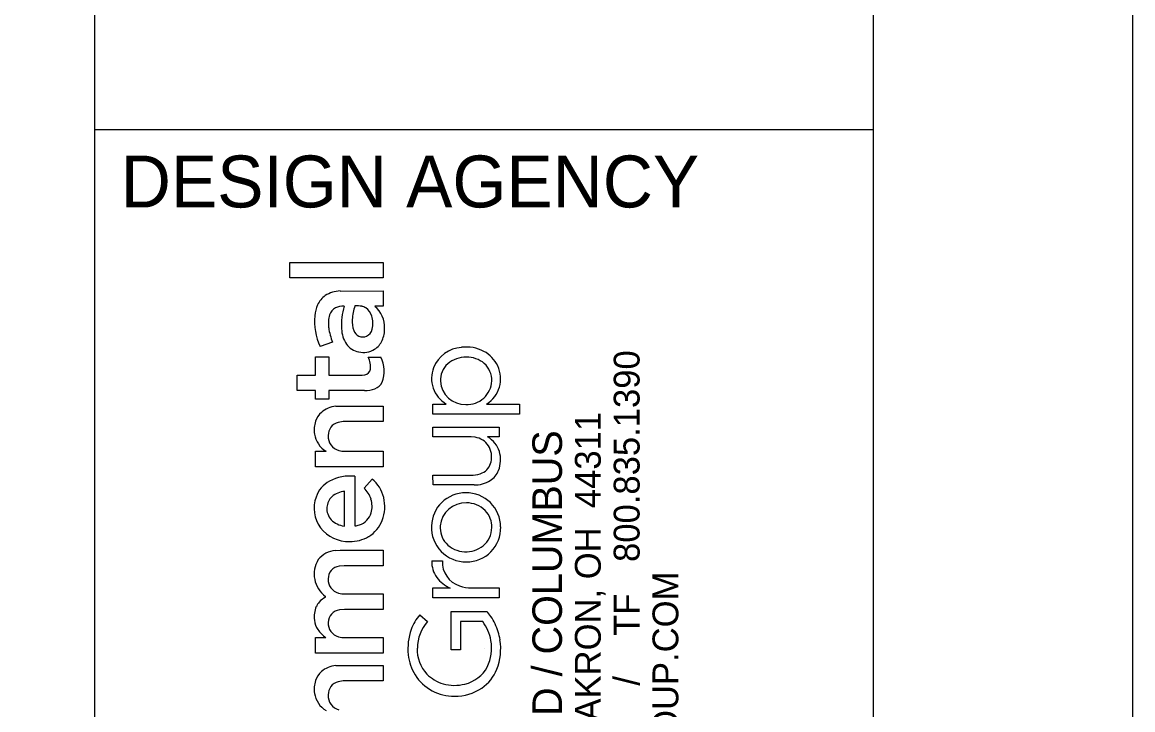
# Model space of a CAD drawing. Extents: x -0.2 to 34, y 0 to 22.
# Drawn here: x 31.86 to 34, y 3.382 to 4.707 of the extents above; entities that cross this region are included whole.
import ezdxf

# ---------------------------------------------------------------- set-up
doc = ezdxf.new("R2010")
doc.units = 0
for name, color, linetype in [('SH_Border', 7, 'Continuous'), ('SH_Cut_Line', 7, 'Continuous'), ('SH_Data', 7, 'Continuous')]:
    doc.layers.add(name, color=color, linetype=linetype)

msp = doc.modelspace()

# ---------------------------------------------------------------- linework, layer by layer
at = {"layer": 'SH_Border'}
for p, q in [((32, 0.5), (32, 21.5)), ((32, 4.5), (33.5, 4.5))]:
    msp.add_line(p, q, dxfattribs=at)
msp.add_lwpolyline([(1.5, 21.5), (33.5, 21.5), (33.5, 0.5), (1.5, 0.5)], close=True, dxfattribs=at)
at = {"layer": 'SH_Cut_Line'}
msp.add_lwpolyline([(0, 0), (34, 0), (34, 22), (0, 22)], close=True, dxfattribs=at)
at = {"layer": 'SH_Data'}
for p, q in [((32.3756, 4.2141), (32.3756, 4.244)), ((32.3756, 4.244), (32.5557, 4.244)), ((32.5557, 4.244), (32.5557, 4.2141)), ((32.5557, 4.2141), (32.3756, 4.2141)), ((32.4727, 4.189), (32.5555, 4.1892)), ((32.5555, 4.1892), (32.5557, 4.1596)), ((32.5557, 4.1596), (32.5397, 4.1596)), ((32.4582, 4.0904), (32.4343, 4.0823)), ((32.4254, 4.027), (32.4255, 4.0621)), ((32.4255, 4.0621), (32.4511, 4.0621)), ((32.4511, 4.0621), (32.4512, 4.027)), ((32.527, 4.0616), (32.5511, 4.0616)), ((32.3896, 3.9972), (32.3896, 4.027)), ((32.3896, 4.027), (32.4254, 4.027)), ((32.4512, 4.027), (32.515, 4.027)), ((32.515, 4.027), (32.52, 4.0275)), ((32.4254, 3.9972), (32.3896, 3.9972)), ((32.4254, 3.9807), (32.4254, 3.9972)), ((32.4511, 3.9807), (32.4254, 3.9807)), ((32.5197, 3.9972), (32.4511, 3.9972)), ((32.4511, 3.9972), (32.4511, 3.9807)), ((32.4644, 3.9669), (32.4729, 3.9673)), ((32.4729, 3.9673), (32.5557, 3.9673)), ((32.5557, 3.9673), (32.5557, 3.9375)), ((32.6515, 3.9521), (32.6515, 3.9711)), ((32.6515, 3.9711), (32.6771, 3.9711)), ((32.7549, 3.9713), (32.8186, 3.9711)), ((32.8186, 3.9711), (32.8184, 3.9521)), ((32.5557, 3.9375), (32.4814, 3.9375)), ((32.8184, 3.9521), (32.6515, 3.9521)), ((32.6515, 3.908), (32.6515, 3.9267)), ((32.6515, 3.9267), (32.7791, 3.9266)), ((32.7791, 3.9266), (32.7791, 3.908)), ((32.7249, 3.908), (32.6515, 3.908)), ((32.7328, 3.9073), (32.7249, 3.908)), ((32.7791, 3.908), (32.7569, 3.908)), ((32.4254, 3.8503), (32.4254, 3.8802)), ((32.4254, 3.8802), (32.4455, 3.8802)), ((32.4822, 3.8802), (32.5557, 3.8802)), ((32.5557, 3.8802), (32.5557, 3.8504)), ((32.5557, 3.8504), (32.4254, 3.8503)), ((32.5011, 3.8321), (32.5012, 3.7366)), ((32.6515, 3.8344), (32.7291, 3.8345)), ((32.6517, 3.8154), (32.6515, 3.8344)), ((32.5188, 3.8093), (32.5342, 3.8266)), ((32.7307, 3.8154), (32.6517, 3.8154)), ((32.4814, 3.7364), (32.4814, 3.803)), ((32.4802, 3.7363), (32.4814, 3.7364)), ((32.4633, 3.6891), (32.4726, 3.6897)), ((32.4726, 3.6897), (32.5556, 3.6897)), ((32.5556, 3.6897), (32.5557, 3.6598)), ((32.4806, 3.6598), (32.471, 3.6588)), ((32.5557, 3.6598), (32.4806, 3.6598)), ((32.6493, 3.6691), (32.6698, 3.6691)), ((32.6515, 3.598), (32.6515, 3.617)), ((32.6515, 3.617), (32.6848, 3.617)), ((32.726, 3.617), (32.7791, 3.617)), ((32.7791, 3.617), (32.779, 3.598)), ((32.4444, 3.5992), (32.4446, 3.6007)), ((32.4822, 3.6055), (32.5557, 3.6055)), ((32.5557, 3.6055), (32.5557, 3.5757)), ((32.779, 3.598), (32.6515, 3.598)), ((32.4809, 3.5757), (32.4714, 3.5747)), ((32.5557, 3.5757), (32.4809, 3.5757)), ((32.6264, 3.5655), (32.6411, 3.5524)), ((32.6868, 3.5718), (32.7552, 3.5719)), ((32.6868, 3.4978), (32.6868, 3.5718)), ((32.7045, 3.5524), (32.7043, 3.4978)), ((32.7474, 3.5523), (32.7045, 3.5524)), ((32.4254, 3.4915), (32.4254, 3.5214)), ((32.4254, 3.5214), (32.4451, 3.5214)), ((32.4821, 3.5214), (32.5557, 3.5214)), ((32.5557, 3.5214), (32.5557, 3.4916)), ((32.5557, 3.4916), (32.4254, 3.4915)), ((32.7043, 3.4978), (32.6868, 3.4978)), ((32.75, 3.5), (32.75, 3.5)), ((32.4644, 3.4674), (32.4729, 3.4678)), ((32.4729, 3.4678), (32.5557, 3.4678)), ((32.5557, 3.4678), (32.5557, 3.438)), ((32.5557, 3.438), (32.4814, 3.438))]:
    msp.add_line(p, q, dxfattribs=at)
msp.add_lwpolyline([(32.3756, 4.2141), (32.3756, 4.244), (32.5557, 4.244), (32.5557, 4.2141)], close=True, dxfattribs=at)
for points in [[(32.4727, 4.189), (32.5555, 4.1892), (32.5557, 4.1596)], [(32.5557, 4.1596), (32.5397, 4.1596)], [(32.4582, 4.0904), (32.4343, 4.0823)], [(32.5197, 3.9972), (32.4511, 3.9972), (32.4511, 3.9807), (32.4254, 3.9807), (32.4254, 3.9972), (32.3896, 3.9972), (32.3896, 4.027), (32.4254, 4.027), (32.4255, 4.0621), (32.4511, 4.0621), (32.4512, 4.027), (32.515, 4.027), (32.52, 4.0275)], [(32.527, 4.0616), (32.5511, 4.0616)], [(32.4644, 3.9669), (32.4729, 3.9673), (32.5557, 3.9673), (32.5557, 3.9375), (32.4814, 3.9375)], [(32.7549, 3.9713), (32.8186, 3.9711), (32.8184, 3.9521), (32.6515, 3.9521)], [(32.6515, 3.9521), (32.6515, 3.9711), (32.6771, 3.9711)], [(32.7328, 3.9073), (32.7249, 3.908), (32.6515, 3.908), (32.6515, 3.9267), (32.7791, 3.9266), (32.7791, 3.908), (32.7569, 3.908)], [(32.4254, 3.8503), (32.4254, 3.8802), (32.4455, 3.8802)], [(32.4822, 3.8802), (32.5557, 3.8802), (32.5557, 3.8504), (32.4254, 3.8503)], [(32.5011, 3.8321), (32.5012, 3.7366)], [(32.7307, 3.8154), (32.6517, 3.8154), (32.6515, 3.8344), (32.7291, 3.8345)], [(32.5188, 3.8093), (32.5342, 3.8266)], [(32.4802, 3.7363), (32.4814, 3.7364), (32.4814, 3.803)], [(32.4633, 3.6891), (32.4726, 3.6897), (32.5556, 3.6897), (32.5557, 3.6598), (32.4806, 3.6598), (32.471, 3.6588)], [(32.6493, 3.6691), (32.6698, 3.6691)], [(32.6515, 3.598), (32.6515, 3.617), (32.6848, 3.617)], [(32.726, 3.617), (32.7791, 3.617), (32.779, 3.598), (32.6515, 3.598)], [(32.4444, 3.5992), (32.4446, 3.6007)], [(32.4822, 3.6055), (32.5557, 3.6055), (32.5557, 3.5757), (32.4809, 3.5757), (32.4714, 3.5747)], [(32.6264, 3.5655), (32.6411, 3.5524)], [(32.7474, 3.5523), (32.7045, 3.5524), (32.7043, 3.4978), (32.6868, 3.4978), (32.6868, 3.5718), (32.7552, 3.5719)], [(32.4254, 3.4915), (32.4254, 3.5214), (32.4451, 3.5214)], [(32.4821, 3.5214), (32.5557, 3.5214), (32.5557, 3.4916), (32.4254, 3.4915)], [(32.4644, 3.4674), (32.4729, 3.4678), (32.5557, 3.4678), (32.5557, 3.438), (32.4814, 3.438)]]:
    msp.add_lwpolyline(points, dxfattribs=at)
for centre, radius, start, end in [((32.4685, 4.1447), 0.043, 124.537, 155.6594), ((32.4685, 4.1447), 0.043, 124.537, 155.6594), ((32.4745, 4.1326), 0.0565, 91.8942, 122.6317), ((32.4745, 4.1326), 0.0565, 91.8942, 122.6317), ((32.4882, 4.1361), 0.0646, 155.9764, 175.3149), ((32.4882, 4.1361), 0.0646, 155.9764, 175.3149), ((32.4753, 4.1356), 0.024, 119.4252, 161.6629), ((32.4753, 4.1356), 0.024, 119.4252, 161.6629), ((32.4779, 4.1278), 0.0321, 85.3802, 116.6222), ((32.4779, 4.1278), 0.0321, 85.3802, 116.6222), ((32.5879, 4.1251), 0.1129, 162.0821, 184.5285), ((32.5879, 4.1251), 0.1129, 162.0821, 184.5285), ((32.5801, 4.1313), 0.0841, 159.8366, 178.0362), ((32.5801, 4.1313), 0.0841, 159.8366, 178.0362), ((32.5051, 4.1074), 0.053, 79.6696, 94.2322), ((32.5051, 4.1074), 0.053, 79.6696, 94.2322), ((32.5089, 4.1364), 0.0238, 56.8913, 76.2149), ((32.5089, 4.1364), 0.0238, 56.8913, 76.2149), ((32.5052, 4.1318), 0.0297, 17.5984, 55.7282), ((32.5052, 4.1318), 0.0297, 17.5984, 55.7282), ((32.5055, 4.1191), 0.0529, 358.0746, 49.762), ((32.5055, 4.1191), 0.0529, 358.0746, 49.762), ((32.5364, 4.1308), 0.113, 174.6101, 205.3899), ((32.5364, 4.1308), 0.113, 174.6101, 205.3899), ((32.5076, 4.1265), 0.0576, 163.1369, 188.1675), ((32.5076, 4.1265), 0.0576, 163.1369, 188.1675), ((32.5466, 4.1303), 0.0506, 175.5903, 199.8857), ((32.5466, 4.1303), 0.0506, 175.5903, 199.8857), ((32.4916, 4.1264), 0.0443, 345.9408, 18.9919), ((32.4916, 4.1264), 0.0443, 345.9408, 18.9919), ((32.5473, 4.1297), 0.0973, 186.7598, 203.7981), ((32.5473, 4.1297), 0.0973, 186.7598, 203.7981), ((32.5328, 4.1187), 0.0575, 182.5676, 213.7144), ((32.5328, 4.1187), 0.0575, 182.5676, 213.7144), ((32.5164, 4.1189), 0.0184, 198.2844, 293.3081), ((32.5164, 4.1189), 0.0184, 198.2844, 293.3081), ((32.5152, 4.1199), 0.0199, 295.2883, 347.4639), ((32.5152, 4.1199), 0.0199, 295.2883, 347.4639), ((32.5019, 4.1168), 0.0566, 336.016, 0.5951), ((32.5019, 4.1168), 0.0566, 336.016, 0.5951), ((32.5175, 4.1097), 0.0394, 303.4436, 336.18), ((32.5175, 4.1097), 0.0394, 303.4436, 336.18), ((32.5149, 4.1078), 0.0366, 215.0668, 259.8133), ((32.5149, 4.1078), 0.0366, 215.0668, 259.8133), ((32.5175, 4.1131), 0.0423, 257.5256, 300.882), ((32.5175, 4.1131), 0.0423, 257.5256, 300.882), ((32.7108, 4.0182), 0.0624, 93.9866, 158.3119), ((32.7108, 4.0182), 0.0624, 93.9866, 158.3119), ((32.7156, 4.0065), 0.0746, 62.6889, 97.0135), ((32.7156, 4.0065), 0.0746, 62.6889, 97.0135), ((32.7212, 4.0191), 0.0608, 25.0657, 61.9602), ((32.7212, 4.0191), 0.0608, 25.0657, 61.9602), ((32.4863, 4.042), 0.0452, 10.1545, 25.723), ((32.4863, 4.042), 0.0452, 10.1545, 25.723), ((32.4957, 4.0436), 0.0356, 351.914, 10.2059), ((32.4957, 4.0436), 0.0356, 351.914, 10.2059), ((32.503, 4.0351), 0.0549, 336.589, 28.8991), ((32.503, 4.0351), 0.0549, 336.589, 28.8991), ((32.7092, 4.0167), 0.0434, 132.3289, 182.0949), ((32.7092, 4.0167), 0.0434, 132.3289, 182.0949), ((32.7138, 4.0102), 0.0513, 87.8965, 131.1812), ((32.7138, 4.0102), 0.0513, 87.8965, 131.1812), ((32.7175, 4.0102), 0.0513, 49.9089, 92.0363), ((32.7175, 4.0102), 0.0513, 49.9089, 92.0363), ((32.7215, 4.0173), 0.0433, 358.0487, 47.9447), ((32.7215, 4.0173), 0.0433, 358.0487, 47.9447), ((32.7245, 4.02), 0.0574, 301.9776, 25.6418), ((32.7245, 4.02), 0.0574, 301.9776, 25.6418), ((32.5184, 4.04), 0.0126, 277.6142, 353.7918), ((32.5184, 4.04), 0.0126, 277.6142, 353.7918), ((32.707, 4.0202), 0.0581, 158.656, 198.171), ((32.707, 4.0202), 0.0581, 158.656, 198.171), ((32.5291, 4.0261), 0.0275, 292.6889, 332.0598), ((32.5291, 4.0261), 0.0275, 292.6889, 332.0598), ((32.7103, 4.0243), 0.0627, 200.8399, 238.0162), ((32.7103, 4.0243), 0.0627, 200.8399, 238.0162), ((32.7135, 4.0181), 0.0478, 183.5974, 271.7045), ((32.7135, 4.0181), 0.0478, 183.5974, 271.7045), ((32.7172, 4.018), 0.0477, 267.3149, 357.4019), ((32.7172, 4.018), 0.0477, 267.3149, 357.4019), ((32.5209, 4.0486), 0.0514, 268.6727, 291.5235), ((32.5209, 4.0486), 0.0514, 268.6727, 291.5235), ((32.4687, 3.9172), 0.0499, 94.9706, 130.2248), ((32.4687, 3.9172), 0.0499, 94.9706, 130.2248), ((32.4787, 3.9211), 0.056, 162.274, 187.7917), ((32.4787, 3.9211), 0.056, 162.274, 187.7917), ((32.4635, 3.9255), 0.0402, 132.2238, 161.6823), ((32.4635, 3.9255), 0.0402, 132.2238, 161.6823), ((32.4811, 3.8915), 0.046, 89.6051, 105.3303), ((32.4811, 3.8915), 0.046, 89.6051, 105.3303), ((32.4748, 3.9116), 0.025, 103.6868, 182.214), ((32.4748, 3.9116), 0.025, 103.6868, 182.214), ((32.4703, 3.9209), 0.0476, 188.9646, 238.6987), ((32.4703, 3.9209), 0.0476, 188.9646, 238.6987), ((32.4774, 3.9085), 0.0276, 175.5844, 255.1382), ((32.4774, 3.9085), 0.0276, 175.5844, 255.1382), ((32.7271, 3.87), 0.0377, 33.5008, 81.3295), ((32.7271, 3.87), 0.0377, 33.5008, 81.3295), ((32.7324, 3.8648), 0.0496, 17.6221, 60.3897), ((32.7324, 3.8648), 0.0496, 17.6221, 60.3897), ((32.4818, 3.9224), 0.0421, 254.0891, 270.5284), ((32.4818, 3.9224), 0.0421, 254.0891, 270.5284), ((32.7241, 3.8695), 0.0405, 346.5618, 31.7539), ((32.7241, 3.8695), 0.0405, 346.5618, 31.7539), ((32.7234, 3.8641), 0.0584, 339.162, 15.6148), ((32.7234, 3.8641), 0.0584, 339.162, 15.6148), ((32.7337, 3.8662), 0.0304, 294.6321, 348.4863), ((32.7337, 3.8662), 0.0304, 294.6321, 348.4863), ((32.4918, 3.7487), 0.0839, 83.6212, 118.2845), ((32.4918, 3.7487), 0.0839, 83.6212, 118.2845), ((32.7275, 3.8808), 0.0463, 271.952, 294.0894), ((32.7275, 3.8808), 0.0463, 271.952, 294.0894), ((32.739, 3.859), 0.042, 303.1039, 338.1561), ((32.739, 3.859), 0.042, 303.1039, 338.1561), ((32.4789, 3.7737), 0.0558, 118.8294, 160.6224), ((32.4789, 3.7737), 0.0558, 118.8294, 160.6224), ((32.4803, 3.7702), 0.0549, 19.0387, 45.4432), ((32.4803, 3.7702), 0.0549, 19.0387, 45.4432), ((32.494, 3.7763), 0.0644, 13.5328, 51.3627), ((32.494, 3.7763), 0.0644, 13.5328, 51.3627), ((32.7321, 3.8726), 0.0571, 268.627, 301.4778), ((32.7321, 3.8726), 0.0571, 268.627, 301.4778), ((32.487, 3.7707), 0.0644, 160.5214, 215.7815), ((32.487, 3.7707), 0.0644, 160.5214, 215.7815), ((32.477, 3.7709), 0.0298, 132.9855, 177.1802), ((32.477, 3.7709), 0.0298, 132.9855, 177.1802), ((32.4844, 3.7607), 0.0424, 94.0131, 130.8806), ((32.4844, 3.7607), 0.0424, 94.0131, 130.8806), ((32.4872, 3.7743), 0.047, 344.6072, 17.0067), ((32.4872, 3.7743), 0.047, 344.6072, 17.0067), ((32.4829, 3.7738), 0.0758, 339.3543, 13.3771), ((32.4829, 3.7738), 0.0758, 339.3543, 13.3771), ((32.7143, 3.7348), 0.0655, 89.4821, 178.7775), ((32.7143, 3.7348), 0.0655, 89.4821, 178.7775), ((32.7158, 3.7341), 0.0662, 0.4227, 90.7613), ((32.7158, 3.7341), 0.0662, 0.4227, 90.7613), ((32.4782, 3.7697), 0.0311, 175.0014, 223.2876), ((32.4782, 3.7697), 0.0311, 175.0014, 223.2876), ((32.714, 3.7324), 0.0485, 87.6883, 175.017), ((32.714, 3.7324), 0.0485, 87.6883, 175.017), ((32.7166, 3.7304), 0.0505, 44.912, 90.7591), ((32.7166, 3.7304), 0.0505, 44.912, 90.7591), ((32.4855, 3.7783), 0.0423, 225.0645, 262.797), ((32.4855, 3.7783), 0.0423, 225.0645, 262.797), ((32.499, 3.7718), 0.035, 288.0108, 343.5536), ((32.499, 3.7718), 0.035, 288.0108, 343.5536), ((32.4955, 3.7698), 0.0626, 300.9439, 338.7322), ((32.4955, 3.7698), 0.0626, 300.9439, 338.7322), ((32.7196, 3.7345), 0.0455, 358.3228, 43.8349), ((32.7196, 3.7345), 0.0455, 358.3228, 43.8349), ((32.4891, 3.7752), 0.0687, 217.7434, 271.6561), ((32.4891, 3.7752), 0.0687, 217.7434, 271.6561), ((32.5013, 3.7568), 0.0202, 269.7004, 294.8729), ((32.5013, 3.7568), 0.0202, 269.7004, 294.8729), ((32.7148, 3.7334), 0.0661, 177.5373, 270.9452), ((32.7148, 3.7334), 0.0661, 177.5373, 270.9452), ((32.7108, 3.7331), 0.0453, 175.5147, 221.4205), ((32.7108, 3.7331), 0.0453, 175.5147, 221.4205), ((32.7167, 3.7327), 0.0654, 269.3083, 1.6791), ((32.7167, 3.7327), 0.0654, 269.3083, 1.6791), ((32.7193, 3.7337), 0.0457, 308.9038, 359.3095), ((32.7193, 3.7337), 0.0457, 308.9038, 359.3095), ((32.492, 3.777), 0.0706, 269.2053, 300.3357), ((32.492, 3.777), 0.0706, 269.2053, 300.3357), ((32.714, 3.7373), 0.0505, 222.6626, 268.3733), ((32.714, 3.7373), 0.0505, 222.6626, 268.3733), ((32.4664, 3.644), 0.0452, 93.9112, 142.3072), ((32.4664, 3.644), 0.0452, 93.9112, 142.3072), ((32.7157, 3.7386), 0.0518, 266.5531, 308.6725), ((32.7157, 3.7386), 0.0518, 266.5531, 308.6725), ((32.4759, 3.6437), 0.0532, 148.2879, 233.9556), ((32.4759, 3.6437), 0.0532, 148.2879, 233.9556), ((32.6988, 3.6666), 0.0495, 177.1621, 216.2802), ((32.6988, 3.6666), 0.0495, 177.1621, 216.2802), ((32.7173, 3.6664), 0.0476, 176.7699, 252.1504), ((32.7173, 3.6664), 0.0476, 176.7699, 252.1504), ((32.4738, 3.635), 0.024, 96.7576, 181.6251), ((32.4738, 3.635), 0.024, 96.7576, 181.6251), ((32.4758, 3.6324), 0.026, 175.8157, 256.1672), ((32.4758, 3.6324), 0.026, 175.8157, 256.1672), ((32.7098, 3.6755), 0.0637, 216.9153, 246.8862), ((32.7098, 3.6755), 0.0637, 216.9153, 246.8862), ((32.7269, 3.6917), 0.0747, 251.1388, 269.3469), ((32.7269, 3.6917), 0.0747, 251.1388, 269.3469), ((32.4638, 3.5627), 0.0414, 117.9163, 139.243), ((32.4638, 3.5627), 0.0414, 117.9163, 139.243), ((32.4817, 3.6505), 0.045, 254.3463, 270.6103), ((32.4817, 3.6505), 0.045, 254.3463, 270.6103), ((32.4714, 3.5612), 0.0488, 156.0638, 187.3493), ((32.4714, 3.5612), 0.0488, 156.0638, 187.3493), ((32.4619, 3.5645), 0.0387, 139.5245, 154.847), ((32.4619, 3.5645), 0.0387, 139.5245, 154.847), ((32.4742, 3.5506), 0.0243, 96.5532, 179.949), ((32.4742, 3.5506), 0.0243, 96.5532, 179.949), ((32.4646, 3.5597), 0.0418, 186.5579, 213.3885), ((32.4646, 3.5597), 0.0418, 186.5579, 213.3885), ((32.7016, 3.5019), 0.0986, 139.7948, 159.137), ((32.7016, 3.5019), 0.0986, 139.7948, 159.137), ((32.699, 3.5008), 0.0775, 138.258, 179.7006), ((32.699, 3.5008), 0.0775, 138.258, 179.7006), ((32.6789, 3.501), 0.0856, 10.0751, 36.8319), ((32.6789, 3.501), 0.0856, 10.0751, 36.8319), ((32.725, 3.5394), 0.0444, 30.9891, 47.161), ((32.725, 3.5394), 0.0444, 30.9891, 47.161), ((32.6709, 3.5002), 0.1111, 25.3031, 33.9618), ((32.6709, 3.5002), 0.1111, 25.3031, 33.9618), ((32.4789, 3.5708), 0.0598, 214.7043, 235.6872), ((32.4789, 3.5708), 0.0598, 214.7043, 235.6872), ((32.4761, 3.5486), 0.0263, 175.722, 255.7863), ((32.4761, 3.5486), 0.0263, 175.722, 255.7863), ((32.7187, 3.4997), 0.1154, 161.1438, 185.6281), ((32.7187, 3.4997), 0.1154, 161.1438, 185.6281), ((32.6704, 3.4999), 0.1117, 8.8034, 25.3348), ((32.6704, 3.4999), 0.1117, 8.8034, 25.3348), ((32.4819, 3.5652), 0.0438, 253.6672, 270.1498), ((32.4819, 3.5652), 0.0438, 253.6672, 270.1498), ((32.6842, 3.5006), 0.0804, 333.4669, 11.0367), ((32.6842, 3.5006), 0.0804, 333.4669, 11.0367), ((32.6756, 3.4998), 0.1065, 338.2887, 9.2855), ((32.6756, 3.4998), 0.1065, 338.2887, 9.2855), ((32.6934, 3.497), 0.0899, 185.5077, 212.0129), ((32.6934, 3.497), 0.0899, 185.5077, 212.0129), ((32.6881, 3.4973), 0.0668, 176.6658, 223.6912), ((32.6881, 3.4973), 0.0668, 176.6658, 223.6912), ((32.4687, 3.4177), 0.0499, 94.9706, 130.2248), ((32.4687, 3.4177), 0.0499, 94.9706, 130.2248), ((32.4635, 3.426), 0.0402, 132.2238, 161.6823), ((32.4635, 3.426), 0.0402, 132.2238, 161.6823), ((32.6921, 3.4975), 0.0891, 212.7022, 270.714), ((32.6921, 3.4975), 0.0891, 212.7022, 270.714), ((32.6905, 3.5001), 0.0704, 224.0215, 253.88), ((32.6905, 3.5001), 0.0704, 224.0215, 253.88), ((32.6987, 3.4955), 0.0652, 282.8815, 331.8147), ((32.6987, 3.4955), 0.0652, 282.8815, 331.8147), ((32.6984, 3.4917), 0.0824, 305.0306, 337.6757), ((32.6984, 3.4917), 0.0824, 305.0306, 337.6757), ((32.4787, 3.4216), 0.056, 162.274, 187.7917), ((32.4787, 3.4216), 0.056, 162.274, 187.7917), ((32.4748, 3.4121), 0.025, 103.6868, 182.214), ((32.4748, 3.4121), 0.025, 103.6868, 182.214), ((32.4811, 3.392), 0.046, 89.6051, 105.3303), ((32.4811, 3.392), 0.046, 89.6051, 105.3303), ((32.6932, 3.5125), 0.0831, 254.4535, 283.9512), ((32.6932, 3.5125), 0.0831, 254.4535, 283.9512), ((32.6943, 3.4998), 0.0914, 269.3273, 304.1963), ((32.6943, 3.4998), 0.0914, 269.3273, 304.1963), ((32.4703, 3.4214), 0.0476, 188.9646, 238.6987), ((32.4703, 3.4214), 0.0476, 188.9646, 238.6987), ((32.4774, 3.409), 0.0276, 175.5844, 255.1382), ((32.4774, 3.409), 0.0276, 175.5844, 255.1382)]:
    msp.add_arc(centre, radius, start, end, dxfattribs=at)

# ---------------------------------------------------------------- texts
msp.add_text('DESIGN AGENCY', height=0.1, dxfattribs=at).set_placement((32.05, 4.35))
for s, height, p in [('800.835.1390', 0.049846, (33.0497, 3.6671)), ('450 GRANT ST., AKRON, OH  44311', 0.049846, (32.9749, 2.8374)), ('AKRON / CLEVELAND / COLUMBUS', 0.056969, (32.9001, 2.638)), ('ENVDESIGNGROUP.COM', 0.049846, (33.1244, 2.8374)), ('TF', 0.04985, (33.0497, 3.5246)), ('/  ', 0.04985, (33.0497, 3.4288))]:
    msp.add_text(s, height=height, rotation=90, dxfattribs=at).set_placement(p)

doc.saveas('drawing.dxf')
